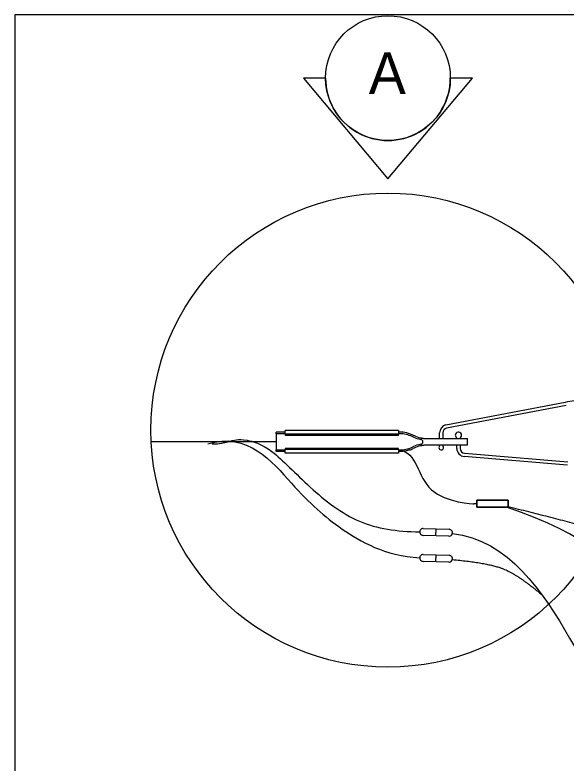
# Model space of a CAD drawing. Extents: x 99862 to 104211, y 98939 to 102076.
# Drawn here: x 99862 to 100127, y 101715.8 to 102075.5 of the extents above; entities that cross this region are included whole.
import ezdxf

# ---------------------------------------------------------------- set-up
doc = ezdxf.new("R2010")
doc.units = 0
for name, color, linetype in [('Level 1', 7, 'Continuous'), ('Level 12', 7, 'Continuous'), ('Level 13', 7, 'Continuous'), ('Level 14', 7, 'Continuous'), ('Level 15', 7, 'Continuous'), ('Level 16', 7, 'Continuous'), ('Level 17', 7, 'Continuous'), ('Level 20', 7, 'Continuous')]:
    doc.layers.add(name, color=color, linetype=linetype)

msp = doc.modelspace()

# ---------------------------------------------------------------- linework, layer by layer
at = {"layer": 'Level 1'}
msp.add_lwpolyline([(99862, 99999.5), (103151, 99999.5), (103151, 102075.5), (99862, 102075.5)], close=True, dxfattribs=at)
at = {"layer": 'Level 12'}
msp.add_line((99987.67, 101870.23), (99927.52, 101870.23), dxfattribs=at)
for points, degree in [([(100046.86, 101866.32), (100055.41, 101865.25), (100055.52, 101841.45), (100082.73, 101840.41), (100082.73, 101840.41)], 3), ([(100084.14, 101840.42), (100083.67, 101840.42), (100083.2, 101840.42), (100082.73, 101840.41)], 2), ([(100176.93, 101638.26), (100173.89, 101734.54), (100164.15, 101799.98), (100138.47, 101825.12), (100098.36, 101838.8)], 3), ([(100240.57, 101813.83), (100191.29, 101813.83), (100136.84, 101829.72), (100099.22, 101838.98)], 2), ([(100072.35, 101826.16), (100099.14, 101823.34), (100133.1, 101771.89), (100157.98, 101718.14), (100226.04, 101726.6), (100230.75, 101770.54)], 3), ([(100072.34, 101813.61), (100091.2, 101811.91), (100105.21, 101805.28), (100115.57, 101796.57)], 2)]:
    msp.add_open_spline(points, degree=degree, dxfattribs=at)
at = {"layer": 'Level 13'}
for p, q in [((99987.67, 101874.13), (99987.67, 101874.91)), ((99987.67, 101874.13), (99987.67, 101866.32)), ((100053.61, 101872.52), (100053.09, 101872.77)), ((100053.41, 101873.47), (100053.94, 101873.23)), ((100079.67, 101868.67), (100079.67, 101871.79)), ((100053.09, 101867.69), (100053.61, 101867.93)), ((100053.94, 101867.22), (100053.41, 101866.98)), ((99987.67, 101865.54), (99987.67, 101866.32))]:
    msp.add_line(p, q, dxfattribs=at)
for centre, radius, start, end in [((100046.86, 101859.29), 14.84, 89.1259, 90.0005), ((100046.86, 101859.29), 14.84, 65.1843, 89.1259), ((100046.86, 101859.29), 15.63, 65.1843, 71.7272), ((100060.49, 101887.42), 16.41, 245.1843, 257.8028), ((100060.49, 101887.42), 15.62, 245.1843, 257.1826), ((100046.86, 101881.16), 14.84, 270, 294.8157), ((100046.86, 101881.16), 15.63, 288.2748, 294.8157), ((100060.49, 101853.04), 16.41, 102.1969, 114.8157), ((100060.49, 101853.04), 15.63, 102.8171, 114.8157)]:
    msp.add_arc(centre, radius, start, end, dxfattribs=at)
for points, degree in [([(99991.88, 101874.91), (99989.77, 101874.91), (99987.67, 101874.91)], 2), ([(99991.88, 101874.13), (99990.48, 101874.13), (99989.07, 101874.13), (99987.67, 101874.13)], 2), ([(100046.86, 101874.92), (100046.64, 101874.92), (100046.43, 101874.92)], 2), ([(100046.86, 101874.13), (100046.71, 101874.13), (100046.57, 101874.13), (100046.43, 101874.13)], 2), ([(100047.1, 101874.92), (100046.98, 101874.92), (100046.86, 101874.92)], 2), ([(100051.75, 101874.13), (100051, 101874.38), (100050.24, 101874.57), (100048.68, 101874.83), (100047.89, 101874.9), (100047.1, 101874.92)], 3), ([(100057.03, 101872.18), (100057.18, 101872.14), (100057.33, 101872.11), (100057.63, 101872.05), (100057.78, 101872.03), (100058.05, 101871.98), (100058.17, 101871.96), (100058.33, 101871.94), (100058.37, 101871.93), (100058.46, 101871.92), (100058.5, 101871.92), (100058.56, 101871.91), (100058.62, 101871.9), (100058.66, 101871.9), (100058.67, 101871.9), (100058.67, 101871.9), (100058.68, 101871.9), (100058.68, 101871.9), (100058.68, 101871.9), (100058.68, 101871.9), (100058.68, 101871.9), (100058.68, 101871.9), (100058.69, 101871.89), (100058.72, 101871.89), (100058.78, 101871.88), (100058.83, 101871.88), (100058.95, 101871.87), (100059.02, 101871.86), (100059.18, 101871.85), (100059.27, 101871.84), (100059.47, 101871.82), (100059.58, 101871.82), (100059.81, 101871.8), (100059.94, 101871.8), (100060.21, 101871.79), (100060.35, 101871.79), (100060.49, 101871.79)], 3), ([(100060.49, 101871.79), (100060.72, 101871.79), (100060.95, 101871.79), (100061.31, 101871.79), (100061.43, 101871.79), (100061.61, 101871.79), (100061.74, 101871.79), (100061.86, 101871.79), (100062.41, 101871.79), (100063.88, 101871.79), (100067.32, 101871.79), (100071.25, 101871.79), (100074.45, 101871.79), (100075.8, 101871.79), (100076.23, 101871.79), (100076.47, 101871.79), (100076.6, 101871.79), (100076.9, 101871.79), (100077.14, 101871.79), (100077.5, 101871.79), (100077.62, 101871.79), (100077.86, 101871.79), (100078.08, 101871.79), (100078.39, 101871.79), (100078.59, 101871.79), (100078.86, 101871.79), (100079.02, 101871.79), (100079.23, 101871.79), (100079.29, 101871.79), (100079.4, 101871.79), (100079.45, 101871.79), (100079.57, 101871.79), (100079.63, 101871.79), (100079.66, 101871.79), (100079.66, 101871.79), (100079.67, 101871.79), (100079.67, 101871.79), (100079.67, 101871.79), (100079.67, 101871.79), (100079.67, 101871.79), (100079.67, 101871.79)], 3), ([(100060.49, 101868.67), (100060.2, 101868.67), (100059.94, 101868.66), (100059.58, 101868.64), (100059.47, 101868.63), (100059.27, 101868.62), (100059.18, 101868.61), (100059.02, 101868.6), (100058.95, 101868.59), (100058.84, 101868.58), (100058.79, 101868.57), (100058.72, 101868.56), (100058.7, 101868.56), (100058.67, 101868.56), (100058.68, 101868.56), (100058.68, 101868.56), (100058.68, 101868.56), (100058.68, 101868.56), (100058.68, 101868.56), (100058.68, 101868.56), (100058.67, 101868.56), (100058.66, 101868.56), (100058.64, 101868.55), (100058.59, 101868.55), (100058.57, 101868.55), (100058.5, 101868.54), (100058.46, 101868.53), (100058.38, 101868.52), (100058.23, 101868.5), (100058.05, 101868.47), (100057.78, 101868.43), (100057.64, 101868.4), (100057.33, 101868.34), (100057.18, 101868.31), (100057.03, 101868.28)], 3), ([(100079.67, 101868.67), (100079.67, 101868.67), (100079.67, 101868.67), (100079.67, 101868.67), (100079.67, 101868.67), (100079.67, 101868.67), (100079.67, 101868.67), (100079.66, 101868.67), (100079.65, 101868.67), (100079.62, 101868.67), (100079.57, 101868.67), (100079.47, 101868.67), (100079.3, 101868.67), (100079.1, 101868.67), (100079.03, 101868.67), (100078.87, 101868.67), (100078.7, 101868.67), (100078.51, 101868.67), (100078.31, 101868.67), (100078, 101868.67), (100077.66, 101868.67), (100077.3, 101868.67), (100077.18, 101868.67), (100076.93, 101868.67), (100076.81, 101868.67), (100076.56, 101868.67), (100076.44, 101868.67), (100076.2, 101868.67), (100075.83, 101868.67), (100074.47, 101868.67), (100071.28, 101868.67), (100067.35, 101868.67), (100063.91, 101868.67), (100062.43, 101868.67), (100061.88, 101868.67), (100061.82, 101868.67), (100061.69, 101868.67), (100061.51, 101868.67), (100061.2, 101868.67), (100060.96, 101868.67), (100060.72, 101868.67), (100060.61, 101868.67), (100060.49, 101868.67)], 3), ([(99987.67, 101866.32), (99989.07, 101866.32), (99990.47, 101866.32), (99991.88, 101866.32)], 2), ([(99991.88, 101865.54), (99989.77, 101865.54), (99987.67, 101865.54)], 2), ([(100046.43, 101866.32), (100046.57, 101866.32), (100046.71, 101866.32), (100046.86, 101866.32)], 2), ([(100046.86, 101865.54), (100046.64, 101865.54), (100046.43, 101865.54)], 2), ([(100051.76, 101866.33), (100050.97, 101866.07), (100050.16, 101865.87), (100048.52, 101865.6), (100047.69, 101865.54), (100046.86, 101865.54)], 3)]:
    msp.add_open_spline(points, degree=degree, dxfattribs=at)
at = {"layer": 'Level 14'}
for p, q in [((100046.43, 101875.7), (99991.88, 101875.7)), ((99991.88, 101873.98), (99991.88, 101875.7)), ((100046.43, 101875.7), (100046.43, 101873.98)), ((100046.43, 101873.98), (99991.88, 101873.98)), ((99991.88, 101873.98), (99991.88, 101873.35)), ((100046.43, 101873.35), (99991.88, 101873.35)), ((100046.43, 101873.35), (100046.43, 101873.98)), ((100046.43, 101867.1), (99991.88, 101867.1)), ((99991.88, 101867.1), (99991.88, 101866.48)), ((100046.43, 101866.48), (100046.43, 101867.1)), ((100046.43, 101866.48), (99991.88, 101866.48)), ((99991.88, 101864.76), (99991.88, 101866.48)), ((100046.43, 101864.76), (99991.88, 101864.76)), ((100046.43, 101866.48), (100046.43, 101864.76))]:
    msp.add_line(p, q, dxfattribs=at)
at = {"layer": 'Level 15'}
for p, q in [((100069.19, 101878.38), (100126.63, 101889.23)), ((100127.01, 101887.71), (100069.57, 101876.87)), ((100066.23, 101871.79), (100066.23, 101874.59)), ((100067.79, 101874.59), (100067.79, 101871.79)), ((100067.79, 101874.59), (100067.79, 101874.59)), ((100069.57, 101876.87), (100069.57, 101876.87)), ((100074.49, 101872.15), (100074.49, 101872.15)), ((100074.49, 101871.79), (100074.49, 101872.15)), ((100076.05, 101872.15), (100076.05, 101871.79)), ((100066.23, 101868.22), (100066.23, 101868.67)), ((100066.23, 101868.22), (100066.23, 101868.22)), ((100067.79, 101868.67), (100067.79, 101868.22)), ((100074.49, 101867.08), (100074.49, 101868.67)), ((100076.05, 101868.67), (100076.05, 101867.08)), ((100076.05, 101867.08), (100076.05, 101867.08)), ((100078.2, 101864.74), (100078.2, 101864.74)), ((100078.2, 101864.74), (100127.92, 101860.61)), ((100127.79, 101859.05), (100078.07, 101863.19))]:
    msp.add_line(p, q, dxfattribs=at)
msp.add_circle((100041.37, 101875.87), 113.99, dxfattribs=at)
for centre, radius, start, end in [((100132.58, 101865.55), 24.41, 83.055, 104.0887), ((100070.14, 101874.59), 3.91, 104.0887, 180), ((100070.14, 101874.59), 2.34, 104.0887, 180), ((100075.27, 101873.46), 1.52, 300.9586, 180), ((100057.03, 101870.23), 1.15, 270.0002, 90.0002), ((100075.27, 101873.46), 1.52, 180, 239.0414), ((100067.01, 101867.43), 1.11, 134.7602, 180), ((100067.01, 101867.43), 1.11, 180, 45.2398), ((100078.39, 101867.08), 3.91, 180, 265.2438), ((100078.39, 101867.08), 2.34, 180, 265.2438)]:
    msp.add_arc(centre, radius, start, end, dxfattribs=at)
at = {"layer": 'Level 16'}
for points in [[(99954.69, 101869.2), (99973.71, 101875.38), (99997.84, 101845.84), (100016.79, 101828.76), (100039.7, 101815.56), (100056.64, 101814.46)], [(99956.8, 101869.2), (99960.73, 101869.2), (99964.37, 101870.47), (99968.75, 101871.29), (99972.09, 101871.58), (99984.61, 101868.34), (100003.09, 101848.18), (100027.08, 101829.56), (100045.42, 101827.18), (100056.64, 101826.95)]]:
    msp.add_open_spline(points, degree=3, dxfattribs=at)
at = {"layer": 'Level 17'}
for p, q in [((100058.35, 101828.56), (100070.76, 101828.17)), ((100064.42, 101825.04), (100064.56, 101828.37)), ((100070.59, 101824.85), (100058.25, 101825.23)), ((100058.35, 101816.07), (100070.76, 101815.68)), ((100064.42, 101812.55), (100064.56, 101815.88)), ((100070.59, 101812.36), (100058.25, 101812.74))]:
    msp.add_line(p, q, dxfattribs=at)
for points in [[(100084.14, 101838.8), (100099.22, 101838.8), (100099.22, 101840.78), (100099.22, 101842.13), (100084.14, 101842.13), (100084.14, 101840.78)], [(100084.14, 101842.13), (100099.22, 101842.13), (100099.22, 101838.8), (100084.14, 101838.8)]]:
    msp.add_lwpolyline(points, close=True, dxfattribs=at)
for centre, start, end in [((100058.3, 101826.9), 88.2059, 268.2354), ((100070.73, 101826.51), 265.1451, 88.8259), ((100058.3, 101814.41), 88.2059, 268.2354), ((100070.73, 101814.02), 265.1451, 88.8259)]:
    msp.add_arc(centre, 1.66, start, end, dxfattribs=at)
at = {"layer": 'Level 20'}
for p, q in [((100011.37, 102045.14), (100000.77, 102045.14)), ((100000.77, 102045.14), (100041.37, 101996.68)), ((100041.37, 101996.68), (100081.97, 102045.14)), ((100081.97, 102045.14), (100071.37, 102045.14))]:
    msp.add_line(p, q, dxfattribs=at)
msp.add_circle((100041.37, 102045.14), 30, dxfattribs=at)
msp.add_arc((100041.37, 102045.14), 30, 179.9978, 0.0022, dxfattribs=at)

# ---------------------------------------------------------------- texts
msp.add_text('A', height=20, dxfattribs=at).set_placement((100032.13, 102037.52))

doc.saveas('drawing.dxf')
